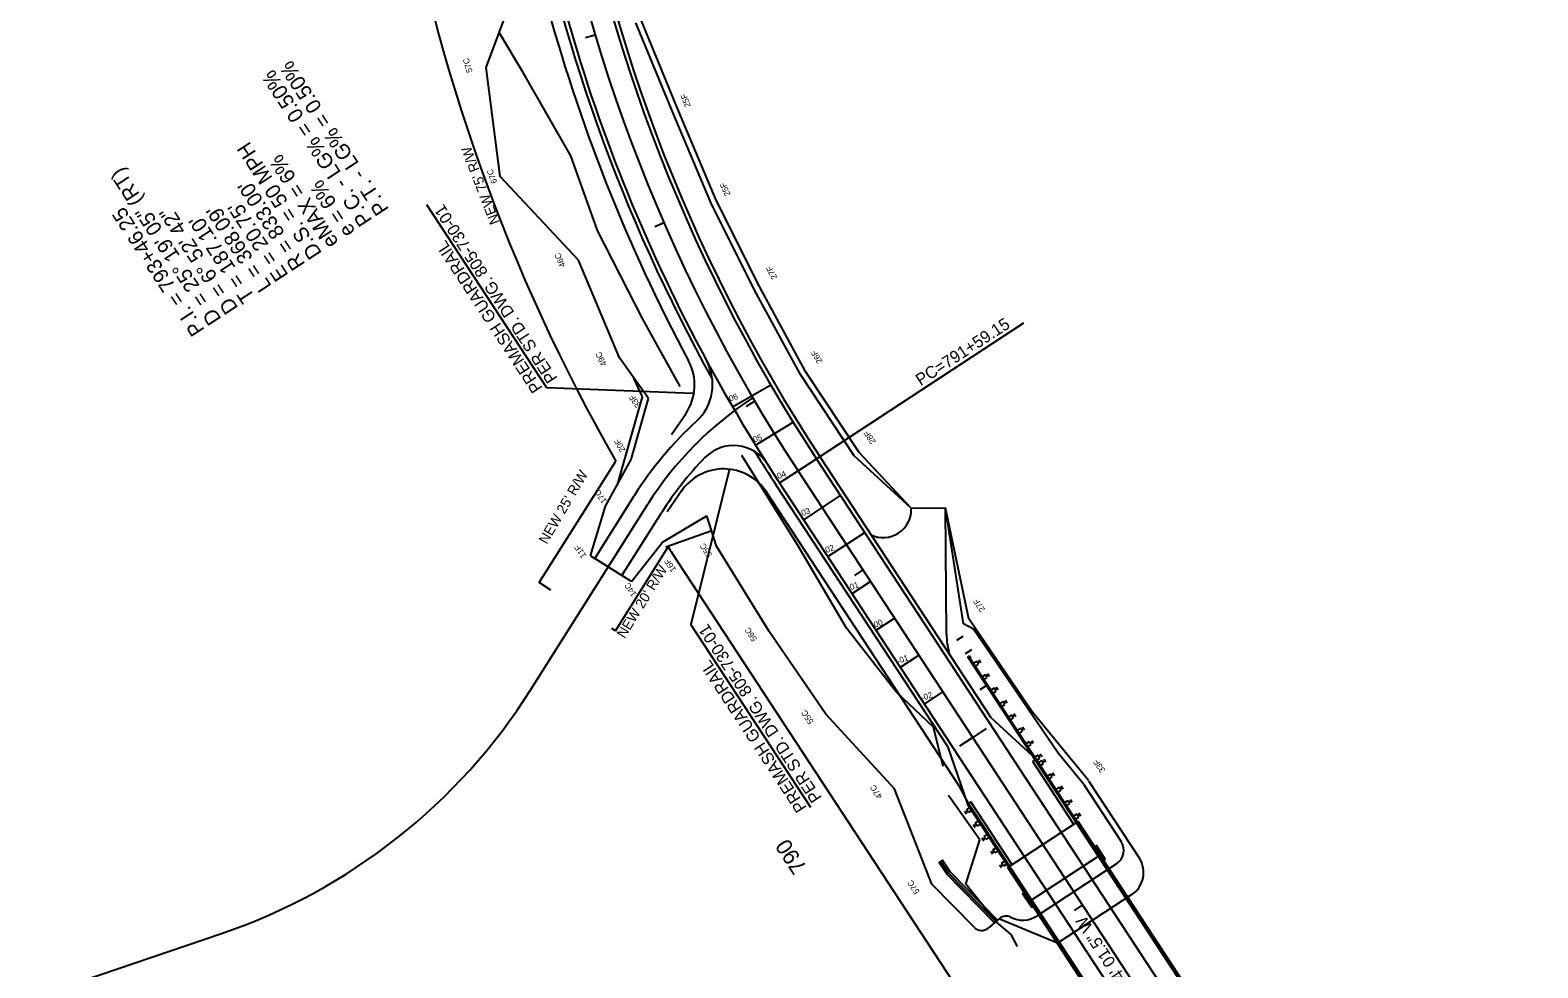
# Model space of a CAD drawing. Extents: x 1551641 to 1624343, y 1119533 to 1136600.
# Drawn here: x 1552089 to 1552842, y 1134301 to 1134769 of the extents above; entities that cross this region are included whole.
import ezdxf

# ---------------------------------------------------------------- set-up
doc = ezdxf.new("R2010")
doc.units = 0
for name, color, linetype in [('Prop CMT Guardrail Graphics', 7, 'Continuous'), ('Prop CMT Pvmt Course 1', 7, 'Continuous'), ('Prop CMT Pvmt Surface', 7, 'Continuous'), ('RD_HC_Cl', 7, 'Continuous'), ('RD_HC_Data', 7, 'Continuous'), ('RD_HC_Data_Tic', 7, 'Continuous'), ('RD_HC_TX_Sta50', 7, 'Continuous'), ('RD_Sketch1', 7, 'Continuous'), ('RD_XS_Base', 7, 'Continuous'), ('RD_XS_Bridge', 7, 'Continuous'), ('RD_XS_EarthShd', 7, 'Continuous'), ('RD_XS_ExGround', 7, 'Continuous'), ('RD_XS_ExPaveRet', 7, 'Continuous'), ('RD_XS_Pave', 7, 'Continuous'), ('RD_XS_PaveOvlay', 7, 'Continuous'), ('RD_XS_PaveShd', 7, 'Continuous'), ('RD_XS_TX_Elev_EX', 7, 'Continuous'), ('RD_XS_TX_Slope', 7, 'Continuous'), ('Scratch_Level_0', 7, 'Continuous')]:
    doc.layers.add(name, color=color, linetype=linetype)

# ---------------------------------------------------------------- blocks, each defined once
blk = doc.blocks.new('Guardrail_MTBBC3_Transition')
at = {"layer": 'RD_XS_Base'}
for p, q in [((37, 0.5), (0, 0.5)), ((0, 0.5), (0, 0)), ((0, 0), (37, 0)), ((3.525, 3.75), (1.775, 3.75)), ((1.775, 0.5), (1.775, 2.5)), ((1.775, 2.5), (3.525, 2.5)), ((3.525, 0.5), (1.775, 0.5)), ((2.65, 2.5), (2.65, 3.75)), ((3.525, 2.5), (3.525, 0.5)), ((11.525, 3.75), (9.775, 3.75)), ((9.775, 0.5), (9.775, 2.5)), ((9.775, 2.5), (11.525, 2.5)), ((11.525, 0.5), (9.775, 0.5)), ((10.65, 2.5), (10.65, 3.75)), ((11.525, 2.5), (11.525, 0.5)), ((19.525, 3.75), (17.775, 3.75)), ((17.775, 0.5), (17.775, 2.5)), ((17.775, 2.5), (19.525, 2.5)), ((19.525, 0.5), (17.775, 0.5)), ((18.65, 2.5), (18.65, 3.75)), ((19.525, 2.5), (19.525, 0.5)), ((27.525, 3.75), (25.775, 3.75)), ((25.775, 0.5), (25.775, 2.5)), ((25.775, 2.5), (27.525, 2.5)), ((27.525, 0.5), (25.775, 0.5)), ((26.65, 2.5), (26.65, 3.75)), ((27.525, 2.5), (27.525, 0.5)), ((30.65, 0.5), (30.65, 0)), ((35.525, 3.75), (33.775, 3.75)), ((33.775, 0.5), (33.775, 2.5)), ((33.775, 2.5), (35.525, 2.5)), ((35.525, 0.5), (33.775, 0.5)), ((34.65, 2.5), (34.65, 3.75)), ((35.525, 2.5), (35.525, 0.5)), ((37, 0), (37, 0.5))]:
    blk.add_line(p, q, dxfattribs=at)
blk = doc.blocks.new('Guardrail_MT3_Leading_with_Buffer')
at = {"layer": 'RD_XS_Base'}
for p, q in [((1.63, 3.8), (-0.12, 3.75)), ((-0.08, 2.5), (1.67, 2.56)), ((-0.02, 0.5), (-0.08, 2.5)), ((60.95, 2.47), (-0.02, 0.5)), ((1.73, 0.56), (-0.02, 0.5)), ((-0.02, 0.5), (0, 0)), ((0, 0), (61.97, 2)), ((0.79, 2.53), (0.75, 3.78)), ((1.67, 2.56), (1.73, 0.56)), ((9.62, 4.06), (7.87, 4.01)), ((7.92, 2.76), (9.66, 2.81)), ((7.98, 0.76), (7.92, 2.76)), ((9.73, 0.81), (7.98, 0.76)), ((8.79, 2.78), (8.75, 4.03)), ((9.66, 2.81), (9.73, 0.81)), ((17.62, 4.32), (15.87, 4.26)), ((15.91, 3.01), (17.66, 3.07)), ((15.98, 1.02), (15.91, 3.01)), ((17.72, 1.07), (15.98, 1.02)), ((16.79, 3.04), (16.75, 4.29)), ((17.66, 3.07), (17.72, 1.07)), ((25.62, 4.58), (23.87, 4.52)), ((23.91, 3.27), (25.66, 3.33)), ((23.97, 1.27), (23.91, 3.27)), ((25.72, 1.33), (23.97, 1.27)), ((24.78, 3.3), (24.74, 4.55)), ((25.66, 3.33), (25.72, 1.33)), ((33.61, 4.84), (31.86, 4.78)), ((31.9, 3.53), (33.65, 3.59)), ((31.97, 1.53), (31.9, 3.53)), ((33.72, 1.59), (31.97, 1.53)), ((32.78, 3.56), (32.74, 4.81)), ((33.65, 3.59), (33.72, 1.59)), ((41.61, 5.09), (39.86, 5.04)), ((39.9, 3.79), (41.65, 3.84)), ((39.96, 1.79), (39.9, 3.79)), ((41.71, 1.85), (39.96, 1.79)), ((40.77, 3.82), (40.73, 5.07)), ((41.65, 3.84), (41.71, 1.85)), ((45.1, -2.3), (44.98, 1.45)), ((49.6, 5.35), (47.85, 5.3)), ((47.89, 4.05), (49.64, 4.1)), ((47.96, 2.05), (47.89, 4.05)), ((49.71, 2.1), (47.96, 2.05)), ((48.77, 4.07), (48.73, 5.32)), ((49.64, 4.1), (49.71, 2.1)), ((57.6, 5.61), (55.85, 5.55)), ((55.89, 4.3), (57.64, 4.36)), ((55.95, 2.31), (55.89, 4.3)), ((57.7, 2.36), (55.95, 2.31)), ((56.76, 4.33), (56.72, 5.58)), ((57.64, 4.36), (57.7, 2.36)), ((61.94, 3), (60.94, 2.97)), ((60.94, 2.97), (60.95, 2.47)), ((61.97, 2), (61.94, 3)), ((63.97, 2.06), (63.85, 5.81)), ((71.96, 2.32), (71.84, 6.07))]:
    blk.add_line(p, q, dxfattribs=at)

msp = doc.modelspace()

# ---------------------------------------------------------------- linework, layer by layer
at = {"layer": 'Prop CMT Guardrail Graphics'}
for p, q in [((1552589.52, 1134404.04), (1552591.19, 1134405.14)), ((1552610.09, 1134372.64), (1552589.52, 1134404.04)), ((1552611.77, 1134373.73), (1552591.19, 1134405.14)), ((1552558.71, 1134383.85), (1552557.04, 1134382.76)), ((1552577.61, 1134351.35), (1552557.04, 1134382.76)), ((1552579.28, 1134352.45), (1552558.71, 1134383.85))]:
    msp.add_line(p, q, dxfattribs=at)
at = {"layer": 'Prop CMT Pvmt Course 1'}
for p, q in [((1552335.31, 1134747.76), (1552323.27, 1134768.07)), ((1552359.07, 1134706.44), (1552335.31, 1134747.76)), ((1552372.24, 1134669.14), (1552359.07, 1134706.44)), ((1552394.91, 1134624.9), (1552372.24, 1134669.14)), ((1552413.56, 1134591.26), (1552394.91, 1134624.9)), ((1552472.06, 1134512.27), (1552444.27, 1134556.88)), ((1552496.56, 1134470.59), (1552472.06, 1134512.27)), ((1552521.43, 1134438.78), (1552496.56, 1134470.59)), ((1552540.08, 1134421.23), (1552521.43, 1134438.78)), ((1552544.83, 1134401.48), (1552540.08, 1134421.23)), ((1552563.11, 1134364.92), (1552547.54, 1134387.09)), ((1552556.07, 1134342.75), (1552563.11, 1134364.92)), ((1552571.35, 1134324.03), (1552556.07, 1134342.75)), ((1552578.84, 1134317.74), (1552571.35, 1134324.03)), ((1552581.92, 1134311.71), (1552578.84, 1134317.74))]:
    msp.add_line(p, q, dxfattribs=at)
at = {"layer": 'Prop CMT Pvmt Surface'}
for p, q in [((1552439.75, 1134581.09), (1552458.76, 1134592.16)), ((1552451.22, 1134561.97), (1552469.93, 1134573.54)), ((1552463.19, 1134543.17), (1552481.59, 1134555.23)), ((1552475.24, 1134524.77), (1552493.65, 1134536.83)), ((1552487.3, 1134506.37), (1552505.7, 1134518.42)), ((1552499.36, 1134487.97), (1552508.56, 1134493.99)), ((1552511.42, 1134469.56), (1552520.62, 1134475.59)), ((1552523.47, 1134451.16), (1552532.67, 1134457.19)), ((1552535.53, 1134432.76), (1552544.73, 1134438.79))]:
    msp.add_line(p, q, dxfattribs=at)
at = {"layer": 'RD_HC_Cl'}
for p, q in [((1552339, 1134439.95), (1552397.43, 1134532.51)), ((1552089.14, 1134285.64), (1552184.7, 1134318.21))]:
    msp.add_line(p, q, dxfattribs=at)
for centre, radius, start, end in [((1552545.41, 1134439.09), 175, 123.11099, 147.73424), ((1552089.55, 1134597.44), 295, 288.81692, 327.73424)]:
    msp.add_arc(centre, radius, start, end, dxfattribs=at)
at = {"layer": 'RD_HC_Data'}
msp.add_line((1552472.39, 1134549.2), (1552585.04, 1134623.01), dxfattribs=at)
at = {"layer": 'RD_HC_Data_Tic'}
for p, q in [((1552371.14, 1134766.81), (1552366.35, 1134765.37)), ((1552405.5, 1134672.96), (1552400.92, 1134670.96)), ((1552450.85, 1134583.9), (1552446.54, 1134581.37)), ((1552504.81, 1134499.72), (1552500.63, 1134496.98)), ((1552559.61, 1134416.08), (1552552.92, 1134411.69)), ((1552566.3, 1134420.46), (1552559.61, 1134416.08)), ((1552614.42, 1134332.43), (1552610.24, 1134329.69))]:
    msp.add_line(p, q, dxfattribs=at)
at = {"layer": 'RD_Sketch1'}
for p, q in [((1552568.73, 1134425.88), (1552483.26, 1134556.32)), ((1552546.98, 1134411.64), (1552461.51, 1134542.07)), ((1552568.73, 1134425.88), (1552591.19, 1134405.14)), ((1552546.98, 1134411.64), (1552557.04, 1134382.76))]:
    msp.add_line(p, q, dxfattribs=at)
for radius, start, end in [(820, 187.91582, 213.23375), (846, 190.21951, 209.06048), (846, 211.8915, 213.23375)]:
    msp.add_arc((1553169.14, 1135005.73), radius, start, end, dxfattribs=at)
at = {"layer": 'RD_XS_Base'}
for p, q in [((1552409.3, 1134567.38), (1552416.34, 1134577.71)), ((1552414.43, 1134539.38), (1552407.15, 1134528.69)), ((1552552.99, 1134391.51), (1552456.5, 1134538.79)), ((1552557.75, 1134382.58), (1552552.99, 1134391.51))]:
    msp.add_line(p, q, dxfattribs=at)
for centre, radius, start, end in [((1553169.14, 1135005.73), 852, 194.90936, 208.12621), ((1552395.27, 1134592.06), 25.5, 325.73561, 28.12621), ((1552435.26, 1134524.66), 25.5, 33.23375, 145.73561)]:
    msp.add_arc(centre, radius, start, end, dxfattribs=at)
at = {"layer": 'RD_XS_Bridge'}
for p, q in [((1552547.47, 1134348.34), (1552543.5, 1134354.4)), ((1552548.25, 1134348.97), (1552544.34, 1134354.94)), ((1552546.69, 1134347.71), (1552542.67, 1134353.85)), ((1552570.64, 1134323.33), (1552546.69, 1134347.71)), ((1552571.35, 1134324.03), (1552547.47, 1134348.34)), ((1552572.06, 1134324.73), (1552548.25, 1134348.97))]:
    msp.add_line(p, q, dxfattribs=at)
at = {"layer": 'RD_XS_EarthShd'}
for p, q in [((1552841.65, 1134005.71), (1552481.59, 1134555.23)), ((1552823.24, 1133993.65), (1552463.19, 1134543.17))]:
    msp.add_line(p, q, dxfattribs=at)
for radius in [844, 822]:
    msp.add_arc((1553169.14, 1135005.73), radius, 187.91582, 213.23375, dxfattribs=at)
at = {"layer": 'RD_XS_ExGround'}
for p, q in [((1552612.25, 1134374.05), (1552577.12, 1134351.04)), ((1552688.91, 1134256.91), (1552612.18, 1134374.01)), ((1552688.98, 1134256.95), (1552612.25, 1134374.05)), ((1552623.22, 1134357.32), (1552588.08, 1134334.31)), ((1552653.85, 1134233.93), (1552577.12, 1134351.04)), ((1552653.92, 1134233.98), (1552577.19, 1134351.08))]:
    msp.add_line(p, q, dxfattribs=at)
for points in [[(1552688.28, 1134256.49), (1552687.53, 1134257.19), (1552611.9, 1134372.62), (1552611.56, 1134373.6)], [(1552654.55, 1134234.39), (1552654.21, 1134235.36), (1552578.58, 1134350.79), (1552577.82, 1134351.49)]]:
    msp.add_lwpolyline(points, dxfattribs=at)
for points in [[(1552620.47, 1134361.51), (1552624.86, 1134354.82), (1552625.7, 1134355.36), (1552621.31, 1134362.05)], [(1552585.34, 1134338.49), (1552589.73, 1134331.8), (1552588.89, 1134331.25), (1552584.51, 1134337.94)]]:
    msp.add_lwpolyline(points, close=True, dxfattribs=at)
at = {"layer": 'RD_XS_ExPaveRet'}
for p, q in [((1552412.78, 1134728.98), (1552394.23, 1134773.81)), ((1552431.53, 1134684.37), (1552412.78, 1134728.98)), ((1552453.2, 1134641.2), (1552431.53, 1134684.37)), ((1552476.13, 1134598.78), (1552453.2, 1134641.2)), ((1552394.81, 1134586.06), (1552390.51, 1134595.42)), ((1552502.97, 1134558.31), (1552476.13, 1134598.78)), ((1552386.18, 1134555.64), (1552394.81, 1134586.06)), ((1552528.93, 1134530.6), (1552502.97, 1134558.31)), ((1552382.21, 1134542.12), (1552386.18, 1134555.64)), ((1552557.62, 1134475.27), (1552545.93, 1134530.76)), ((1552429.34, 1134519.2), (1552406.33, 1134511.04)), ((1552589.32, 1134428.81), (1552557.62, 1134475.27)), ((1552617.33, 1134394.49), (1552589.32, 1134428.81)), ((1552642.77, 1134355.7), (1552617.52, 1134394.24)), ((1552639.03, 1134337.71), (1552601.85, 1134313.3)), ((1552601.85, 1134313.3), (1552572.67, 1134325.42))]:
    msp.add_line(p, q, dxfattribs=at)
msp.add_arc((1552631.9, 1134348.58), 13, 303.28788, 33.23375, dxfattribs=at)
at = {"layer": 'RD_XS_Pave'}
for p, q in [((1552343.17, 1134493.4), (1552381.46, 1134554.04)), ((1552381.23, 1134469.38), (1552407.63, 1134511.2)), ((1552647.6, 1134144.95), (1552409.65, 1134508.1)), ((1552349.09, 1134489.66), (1552343.17, 1134493.4)), ((1552381.23, 1134469.38), (1552379.53, 1134470.44))]:
    msp.add_line(p, q, dxfattribs=at)
for start, end in [(189.4862, 209.8315), (212.99983, 213.23375)]:
    msp.add_arc((1553169.14, 1135005.73), 908, start, end, dxfattribs=at)
at = {"layer": 'RD_XS_PaveOvlay'}
for p, q in [((1552346.97, 1134590.58), (1552287.09, 1134681.98)), ((1552419.91, 1134587.87), (1552346.97, 1134590.58)), ((1552438.06, 1134549.51), (1552418.97, 1134472.49)), ((1552478.86, 1134381.1), (1552418.97, 1134472.49))]:
    msp.add_line(p, q, dxfattribs=at)
at = {"layer": 'RD_XS_PaveShd'}
for p, q in [((1552370.9, 1134505.46), (1552390.67, 1134536.78)), ((1552384.42, 1134496.92), (1552404.2, 1134528.24)), ((1552528.93, 1134530.6), (1552545.93, 1134530.76)), ((1552528.93, 1134530.6), (1552528.94, 1134530.01)), ((1552546.52, 1134467.69), (1552545.93, 1134530.76)), ((1552384.42, 1134496.92), (1552370.9, 1134505.46))]:
    msp.add_line(p, q, dxfattribs=at)
for centre, radius, start, end in [((1552404.77, 1134592.34), 25, 312.54279, 28.40574), ((1552545.41, 1134439.09), 183, 132.54279, 147.73424), ((1552440.26, 1134541.81), 20, 32.47574, 135.66872), ((1552545.41, 1134439.09), 167, 135.66872, 147.73424), ((1552514.94, 1134529.88), 14, 244.23647, 0.53797), ((1552586.52, 1134468.07), 40, 180.53797, 195.03887)]:
    msp.add_arc(centre, radius, start, end, dxfattribs=at)
at = {"layer": 'RD_XS_TX_Elev_EX'}
for p, q in [((1552316.71, 1134750.51), (1552339.17, 1134810.62)), ((1552410.01, 1134727.82), (1552391.37, 1134772.87)), ((1552323.66, 1134696.21), (1552316.71, 1134750.51)), ((1552428.8, 1134683.11), (1552410.01, 1134727.82)), ((1552362.88, 1134654.39), (1552323.66, 1134696.21)), ((1552450.54, 1134639.82), (1552428.8, 1134683.11)), ((1552383.33, 1134605.6), (1552362.88, 1134654.39)), ((1552473.56, 1134597.24), (1552450.54, 1134639.82)), ((1552397.69, 1134585.24), (1552383.33, 1134605.6)), ((1552500.47, 1134556.65), (1552473.56, 1134597.24)), ((1552389.07, 1134554.82), (1552397.69, 1134585.24)), ((1552376.31, 1134531.61), (1552389.07, 1134554.82)), ((1552528.93, 1134530.6), (1552500.47, 1134556.65)), ((1552368.73, 1134506.83), (1552376.31, 1134531.61)), ((1552555.03, 1134472.85), (1552545.93, 1134530.76)), ((1552404.8, 1134513.62), (1552426.95, 1134526.77)), ((1552431.74, 1134511.62), (1552426.95, 1134526.77)), ((1552389.28, 1134493.86), (1552404.8, 1134513.62)), ((1552368.73, 1134506.83), (1552370.9, 1134505.46)), ((1552457.98, 1134469.04), (1552431.74, 1134511.62)), ((1552389.28, 1134493.86), (1552384.42, 1134496.92)), ((1552486.2, 1134427.75), (1552457.98, 1134469.04)), ((1552559.94, 1134470.09), (1552555.03, 1134472.85)), ((1552576.86, 1134445.31), (1552559.94, 1134470.09)), ((1552602.29, 1134408.18), (1552576.86, 1134445.31)), ((1552520.52, 1134390.46), (1552486.2, 1134427.75)), ((1552615.01, 1134392.6), (1552602.29, 1134408.18)), ((1552615.01, 1134392.6), (1552633.64, 1134364.16)), ((1552539.13, 1134342.88), (1552520.52, 1134390.46)), ((1552631.3, 1134352.93), (1552591.69, 1134326.98)), ((1552560.46, 1134321.17), (1552539.13, 1134342.88)), ((1552572.98, 1134325.68), (1552567.24, 1134320.85))]:
    msp.add_line(p, q, dxfattribs=at)
for centre, radius, start, end in [((1552626.86, 1134359.71), 8.11, 303.23375, 33.23375), ((1552576.2, 1134321.85), 5, 62.69034, 130.07172), ((1552584.51, 1134337.94), 13.11, 242.69034, 303.23375), ((1552564.02, 1134324.68), 5, 224.49241, 310.07172)]:
    msp.add_arc(centre, radius, start, end, dxfattribs=at)
at = {"layer": 'Scratch_Level_0'}
msp.add_line((1552832.44, 1133999.68), (1552472.39, 1134549.2), dxfattribs=at)
msp.add_arc((1553169.14, 1135005.73), 833, 187.91582, 213.23375, dxfattribs=at)

# ---------------------------------------------------------------- block references
at = {"layer": 'RD_XS_Base', "yscale": -1, "rotation": 125.08135631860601}
msp.add_blockref('Guardrail_MT3_Leading_with_Buffer', (1552591.07, 1134404.41), dxfattribs=at)
at = {"layer": 'RD_XS_TX_Elev_EX', "yscale": -1, "rotation": 123.23374605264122}
msp.add_blockref('Guardrail_MTBBC3_Transition', (1552611.35, 1134373.46), dxfattribs=at)
at = {"layer": 'RD_XS_TX_Elev_EX', "rotation": 123.23374605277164}
msp.add_blockref('Guardrail_MTBBC3_Transition', (1552578.03, 1134351.63), dxfattribs=at)

# ---------------------------------------------------------------- texts
at = {"layer": 'Prop CMT Pvmt Surface'}
for s, p in [('06', (1552438.55, 1134583.68)), ('05', (1552450.58, 1134563.27)), ('04', (1552462.55, 1134545.01)), ('03', (1552474.62, 1134526.56)), ('02', (1552486.61, 1134508.14)), ('01', (1552498.82, 1134489.62)), ('00', (1552510.82, 1134470.83)), ('-01', (1552522.35, 1134452.7)), ('-02', (1552534.44, 1134434.21))]:
    msp.add_text(s, height=3, rotation=20.03896, dxfattribs=at).set_placement(p)
at = {"layer": 'RD_HC_Data'}
for s, height, rotation, p in [('P.T. - LG% = 0.50%', 7.5, 123.23375, (1552268.47, 1134679.82)), ('P.C. - LG% = 0.50%', 7.5, 123.23375, (1552260.11, 1134674.34)), ('D.S. = 50 MPH', 7.5, 123.23375, (1552235.01, 1134657.9)), ('    = 25%%d 19\' 05" (RT)', 7.5, 123.23375, (1552184.83, 1134625.01)), ('eMAX = 6%', 7.5, 123.23375, (1552243.38, 1134663.38)), ('e = 6%', 7.5, 123.23375, (1552251.74, 1134668.86)), ("R = 833.00'", 7.5, 123.23375, (1552226.65, 1134652.42)), ('P.I. = 793+46.25', 7.5, 123.23375, (1552176.46, 1134619.53)), ('D = 6%%d 52\' 42"', 7.5, 123.23375, (1552193.19, 1134630.5)), ("L = 368.09'", 7.5, 123.23375, (1552209.92, 1134641.46)), ("E = 20.75'", 7.5, 123.23375, (1552218.28, 1134646.94)), ("T = 187.10'", 7.5, 123.23375, (1552201.56, 1134635.98)), ('D', 7.5, 123.23375, (1552184.83, 1134625.01)), ('PC=791+59.15', 6, 33.23375, (1552533.59, 1134591.42)), ('N 33%%d 14\' 01.5" W', 6, 123.23375, (1552650.4, 1134274.52))]:
    msp.add_text(s, height=height, rotation=rotation, dxfattribs=at).set_placement(p)
at = {"layer": 'RD_HC_TX_Sta50'}
msp.add_text('790', height=8, rotation=123.23375, dxfattribs=at).set_placement((1552477.09, 1134351.18))
at = {"layer": 'RD_XS_Pave'}
for s, rotation, p in [("NEW 75' R/W", 111.01426, (1552323.6, 1134673.36)), ("NEW 25' R/W", 59.57924, (1552346.99, 1134512.2)), ("NEW 20' R/W", 58.26158, (1552385.84, 1134465.16))]:
    msp.add_text(s, height=5, rotation=rotation, dxfattribs=at).set_placement(p)
at = {"layer": 'RD_XS_PaveOvlay'}
for s, p in [('PER STD. DWG. 805-730-01', (1552352.57, 1134595.45)), ('PREMASH GUARDRAIL', (1552345.04, 1134590.52)), ('PER STD. DWG. 805-730-01', (1552484.46, 1134385.96)), ('PREMASH GUARDRAIL', (1552476.93, 1134381.03))]:
    msp.add_text(s, height=6, rotation=123.23375, dxfattribs=at).set_placement(p)
at = {"layer": 'RD_XS_TX_Slope'}
for s, rotation, p in [('57C', 106.66775, (1552310.01, 1134748.5)), ('25F', 110.10687, (1552418.9, 1134731.34)), ('67C', 110.10687, (1552322.31, 1134693.27)), ('25F', 113.546, (1552438.77, 1134687.13)), ('46C', 113.546, (1552356.47, 1134651.59)), ('27F', 116.98511, (1552462.12, 1134645.72)), ('49C', 116.98511, (1552377.1, 1134602.42)), ('26F', 120.42424, (1552484.77, 1134603.82)), ('33F', 124.38155, (1552394.15, 1134581.95)), ('28F', 123.23375, (1552511.34, 1134563.78)), ('20F', 118.35672, (1552386.37, 1134559.49)), ('17C', 122.60119, (1552377.11, 1134534.05)), ('55C', 123.23375, (1552429.67, 1134507.25)), ('11F', 122.60119, (1552366.86, 1134506.8)), ('16F', 122.60119, (1552411.67, 1134499.85)), ('14C', 122.60119, (1552391.98, 1134487.54)), ('27F', 123.23375, (1552565.91, 1134479.98)), ('56C', 123.23375, (1552452.12, 1134465.2)), ('55C', 123.23375, (1552480.35, 1134423.92)), ('33F', 123.23375, (1552625.88, 1134399.72)), ('47C', 123.23375, (1552514.67, 1134386.63)), ('57C', 123.23375, (1552533.28, 1134339.04))]:
    msp.add_text(s, height=3, rotation=rotation, dxfattribs=at).set_placement(p)

doc.saveas('drawing.dxf')
